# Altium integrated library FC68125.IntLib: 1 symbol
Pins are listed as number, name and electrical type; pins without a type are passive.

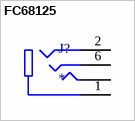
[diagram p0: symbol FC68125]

## FC68125
designator J?
RS PRO 3.5 mm PCB Mount Composite Video Jack Socket, 4Pole; MF: RS Pro; MP: FC68125
footprint CLIFF_FC68125
pins: 1 1S, 2 6SR, 3_1 3T, 3_2 3T, 6 2R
